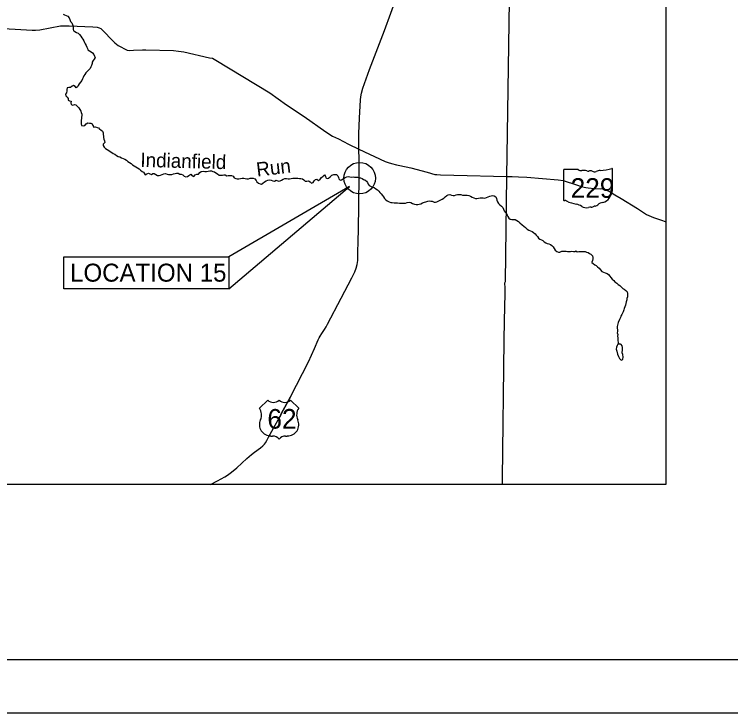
# Model space of a CAD drawing. Extents: x -12.1 to 34, y 0 to 22.
# Drawn here: x 4.28 to 11.05, y 0 to 6.6 of the extents above; entities that cross this region are included whole.
import ezdxf

# ---------------------------------------------------------------- set-up
doc = ezdxf.new("R2010")
doc.units = 0
for name, color, linetype in [('BR_P_Gen_Text', 7, 'Continuous'), ('Default', 7, 'Continuous'), ('GM_X_County_Road', 7, 'Continuous'), ('GM_X_Minor_Lake', 7, 'Continuous'), ('GM_X_Minor_River', 7, 'Continuous'), ('GM_X_Minor_River_Text', 7, 'Continuous'), ('GM_X_State_Route', 7, 'Continuous'), ('GM_X_State_Shield', 7, 'Continuous'), ('GM_X_Township', 7, 'Continuous'), ('GM_X_US_Route', 7, 'Continuous'), ('GM_X_US_Shield', 7, 'Continuous'), ('SH_Border', 7, 'Continuous'), ('SH_Cut_Line', 7, 'Continuous'), ('SH_Text', 7, 'Continuous')]:
    doc.layers.add(name, color=color, linetype=linetype)

msp = doc.modelspace()

# ---------------------------------------------------------------- linework, layer by layer
at = {"layer": 'BR_P_Gen_Text'}
for points in [[(6.3039, 4.3094), (6.3039, 4.0092), (7.4481, 4.9757)], [(4.7437, 4.3094), (6.3039, 4.3094), (6.3039, 4.0092), (4.7437, 4.0092)]]:
    msp.add_lwpolyline(points, close=True, dxfattribs=at)
at = {"layer": 'Default'}
msp.add_circle((7.5423, 5.0544), 0.149, dxfattribs=at)
at = {"layer": 'GM_X_County_Road'}
msp.add_lwpolyline([(6.8881, 2.9878), (6.8011, 2.8263), (6.791, 2.8012)], dxfattribs=at)
at = {"layer": 'GM_X_Minor_Lake'}
for points in [[(9.9847, 3.4834), (9.9767, 3.4716), (9.9714, 3.4577), (9.9688, 3.438), (9.9736, 3.4171), (9.9822, 3.3899), (9.9897, 3.3669), (9.9998, 3.3499), (10.0116, 3.3365), (10.0206, 3.3344), (10.0302, 3.3435), (10.0334, 3.3611), (10.0307, 3.3857), (10.0264, 3.4028), (10.028, 3.4305), (10.029, 3.4546), (10.0242, 3.469), (10.0167, 3.4808), (10.0103, 3.4861), (10.0039, 3.4855)], [(10.0039, 3.4855), (9.9847, 3.4834)]]:
    msp.add_lwpolyline(points, dxfattribs=at)
at = {"layer": 'GM_X_Minor_River'}
for points in [[(4.7387, 6.6063), (4.752, 6.5999), (4.7675, 6.5919), (4.784, 6.585), (4.7968, 6.5711), (4.8022, 6.5556), (4.8086, 6.5364), (4.8193, 6.522), (4.8279, 6.5071), (4.8327, 6.491), (4.8327, 6.4761), (4.8322, 6.4627), (4.8365, 6.4489), (4.8498, 6.4409), (4.8663, 6.4323), (4.8802, 6.4254), (4.8941, 6.4137), (4.9048, 6.3971), (4.916, 6.3822), (4.9235, 6.3688), (4.9342, 6.3528), (4.9406, 6.3378), (4.9481, 6.324), (4.9572, 6.3085), (4.9636, 6.2946), (4.9679, 6.2813), (4.9716, 6.2679), (4.9871, 6.2588), (5.0031, 6.2498), (5.0175, 6.2396), (5.0287, 6.2242), (5.0357, 6.2081), (5.0399, 6.1942), (5.032, 6.1793), (5.0219, 6.1659), (5.0139, 6.152), (5.0123, 6.1376), (5.0054, 6.121), (4.9996, 6.1071), (4.9937, 6.0927), (4.982, 6.0794), (4.9687, 6.0655), (4.9538, 6.051), (4.9432, 6.0345), (4.9341, 6.0211), (4.9278, 6.0061), (4.923, 5.9928), (4.9166, 5.9783), (4.9033, 5.9623), (4.8905, 5.9463), (4.882, 5.9308), (4.8757, 5.9174), (4.8618, 5.9094), (4.8538, 5.9227), (4.8378, 5.9318), (4.8234, 5.9249), (4.8069, 5.9115), (4.792, 5.9104), (4.7765, 5.9077), (4.7739, 5.8933), (4.7744, 5.8789), (4.7707, 5.8628), (4.7596, 5.8489), (4.7639, 5.8329), (4.7777, 5.8217), (4.7847, 5.8073), (4.7852, 5.7913), (4.8002, 5.787), (4.814, 5.7822), (4.8109, 5.7657)], [(4.8109, 5.7657), (4.8152, 5.7518), (4.8301, 5.7459), (4.8461, 5.7502), (4.8599, 5.7481), (4.8722, 5.7347), (4.8872, 5.7198), (4.8978, 5.7043), (4.9059, 5.6883), (4.9102, 5.6744), (4.9139, 5.66), (4.9139, 5.6461), (4.9129, 5.6322), (4.9113, 5.6178), (4.9097, 5.6039), (4.9076, 5.5836), (4.9077, 5.5671), (4.913, 5.5537), (4.9274, 5.5484), (4.9423, 5.5527), (4.9562, 5.5676), (4.9711, 5.5773), (4.9865, 5.5757), (4.9999, 5.5735), (5.0132, 5.5688), (5.0207, 5.5517), (5.0303, 5.5383), (5.0452, 5.5389), (5.0602, 5.533), (5.0745, 5.5309), (5.0815, 5.517), (5.0959, 5.5111), (5.1103, 5.4983), (5.1173, 5.4823), (5.1173, 5.4684), (5.1216, 5.4529), (5.12, 5.4385), (5.1243, 5.4236), (5.1312, 5.4075), (5.1313, 5.3915), (5.1158, 5.376), (5.1158, 5.3621), (5.1265, 5.3482), (5.1404, 5.3344), (5.1564, 5.3242), (5.1703, 5.3157), (5.1842, 5.3077), (5.1991, 5.2976), (5.2124, 5.289), (5.2268, 5.2805), (5.2434, 5.2698), (5.2594, 5.2597), (5.2743, 5.2549), (5.2914, 5.2474), (5.3074, 5.241), (5.3218, 5.2352), (5.3378, 5.224), (5.3511, 5.2133), (5.3656, 5.2032), (5.381, 5.1925), (5.396, 5.1813), (5.4109, 5.1712), (5.4258, 5.1632), (5.4419, 5.1525), (5.4573, 5.1429), (5.4707, 5.1306), (5.4851, 5.1189), (5.4995, 5.1114), (5.5155, 5.0847), (5.531, 5.0943), (5.5453, 5.1008), (5.5587, 5.0944), (5.5731, 5.0885), (5.5869, 5.0997), (5.6002, 5.0992), (5.6136, 5.0896), (5.6301, 5.08), (5.6456, 5.0784), (5.6594, 5.0832), (5.6738, 5.0891), (5.6893, 5.0961), (5.7069, 5.0977), (5.7213, 5.0929), (5.7362, 5.0881), (5.7511, 5.0886), (5.7666, 5.0897), (5.782, 5.0945), (5.7964, 5.0999), (5.8097, 5.1015), (5.8262, 5.1005), (5.8412, 5.0909), (5.855, 5.0919), (5.8694, 5.0866), (5.8839, 5.0727), (5.8993, 5.0679), (5.9142, 5.0695), (5.9286, 5.0808), (5.9451, 5.0931), (5.9601, 5.076), (5.975, 5.0717), (5.9872, 5.0867)], [(5.9872, 5.0867), (6.0032, 5.0937), (6.0171, 5.0931), (6.0314, 5.107), (6.0453, 5.1183), (6.0618, 5.1215), (6.0773, 5.1178), (6.0933, 5.1178), (6.1108, 5.1221), (6.1247, 5.1237), (6.1407, 5.1226), (6.1556, 5.1183), (6.169, 5.1157), (6.1834, 5.1061), (6.1994, 5.0943), (6.2148, 5.0831), (6.2287, 5.0816), (6.2442, 5.0832), (6.258, 5.0858), (6.2719, 5.0848), (6.2852, 5.0763), (6.3001, 5.0784), (6.3172, 5.0811), (6.3305, 5.0806), (6.3449, 5.072), (6.3551, 5.0581), (6.3705, 5.0507), (6.3849, 5.0486), (6.4009, 5.0486), (6.4169, 5.0502), (6.4318, 5.0539), (6.4462, 5.0539), (6.4612, 5.0513), (6.4755, 5.0486), (6.4926, 5.0497), (6.5065, 5.0545), (6.523, 5.0545), (6.5363, 5.054), (6.5507, 5.0476), (6.5635, 5.0321), (6.5715, 5.0183), (6.5865, 5.0071), (6.6003, 5.0007), (6.6137, 4.9991), (6.6275, 5.0076), (6.6435, 5.0183), (6.6573, 5.0295), (6.6739, 5.0349), (6.6888, 5.0376), (6.7048, 5.036), (6.7213, 5.028), (6.7373, 5.0264), (6.7517, 5.0355), (6.7757, 5.0275), (6.7901, 5.0291), (6.8039, 5.0371), (6.8188, 5.0457), (6.8364, 5.0521), (6.8513, 5.0511), (6.8663, 5.0495), (6.8796, 5.0484), (6.8961, 5.0506), (6.911, 5.0543), (6.9254, 5.0549), (6.943, 5.0549), (6.9579, 5.0538), (6.9723, 5.0522), (6.9856, 5.0506), (7.0027, 5.048), (7.0161, 5.0384), (7.0278, 5.025), (7.0433, 5.0256), (7.0598, 5.0288), (7.0747, 5.0197), (7.0881, 5.008), (7.1019, 5.0133), (7.1136, 5.0278), (7.1248, 5.0411), (7.1392, 5.046), (7.1541, 5.0331), (7.168, 5.0438), (7.1813, 5.0604), (7.1962, 5.0732), (7.2105, 5.085), (7.2191, 5.0711), (7.2212, 5.0567), (7.2356, 5.0514), (7.249, 5.0551), (7.2628, 5.0685), (7.2798, 5.0824), (7.2969, 5.0877), (7.3102, 5.0883), (7.3241, 5.0888), (7.3353, 5.0755), (7.3422, 5.0611), (7.3449, 5.0477), (7.3572, 5.0344), (7.371, 5.0376), (7.387, 5.0494), (7.4051, 5.0595), (7.4216, 5.0675)], [(7.4216, 5.0675), (7.4355, 5.0702), (7.4494, 5.0686), (7.4659, 5.0649), (7.4797, 5.0676), (7.4941, 5.0649), (7.508, 5.065), (7.5219, 5.0639), (7.5368, 5.0591), (7.5512, 5.057), (7.5651, 5.05), (7.5784, 5.0431), (7.5928, 5.0378), (7.6083, 5.0276), (7.6173, 5.0127), (7.6232, 4.9993), (7.6312, 4.9849), (7.6499, 4.9743), (7.6654, 4.9684), (7.6787, 4.9647), (7.6963, 4.9551), (7.7102, 4.9449), (7.723, 4.9316), (7.7348, 4.9183), (7.747, 4.9049), (7.7582, 4.8905), (7.7684, 4.8772), (7.7775, 4.8622), (7.7898, 4.8489), (7.8042, 4.8398), (7.8202, 4.8313), (7.8372, 4.8254), (7.8516, 4.8259), (7.8687, 4.8222), (7.8847, 4.8222), (7.9001, 4.8206), (7.9199, 4.8191), (7.9359, 4.818), (7.9513, 4.8175), (7.9769, 4.8191), (7.9934, 4.825), (8.0099, 4.8272), (8.0254, 4.8245), (8.0435, 4.8149), (8.0617, 4.8085), (8.0755, 4.8064), (8.0915, 4.8069), (8.1054, 4.808), (8.1219, 4.8128), (8.1379, 4.8198), (8.1549, 4.8262), (8.1682, 4.83), (8.1864, 4.8369), (8.2007, 4.8396), (8.2157, 4.838), (8.2295, 4.8364), (8.2461, 4.8274), (8.2599, 4.8274), (8.2738, 4.8306), (8.2903, 4.8386), (8.3041, 4.8461), (8.3228, 4.8552), (8.3382, 4.8664), (8.3521, 4.8777), (8.367, 4.8894), (8.3808, 4.8964), (8.3952, 4.8991), (8.4107, 4.8927), (8.4261, 4.8895), (8.44, 4.8906), (8.4549, 4.8959), (8.4688, 4.9002), (8.4837, 4.9007), (8.5008, 4.8986), (8.5141, 4.8949), (8.529, 4.8922), (8.5455, 4.8933), (8.5589, 4.8949), (8.5759, 4.8912), (8.5903, 4.8843), (8.6079, 4.8752), (8.6218, 4.8677), (8.6383, 4.8608), (8.6517, 4.8608), (8.6676, 4.8646), (8.6815, 4.8694), (8.6948, 4.8699), (8.7098, 4.8678), (8.7263, 4.8662), (8.7593, 4.878), (8.7732, 4.885), (8.7865, 4.8877), (8.8003, 4.8909), (8.8147, 4.8882), (8.8291, 4.877), (8.8361, 4.861), (8.8398, 4.845), (8.8468, 4.8295), (8.8564, 4.8161), (8.8676, 4.8028), (8.8826, 4.7884)], [(8.8826, 4.7884), (8.8981, 4.7761), (8.9023, 4.7628), (8.9088, 4.7468), (8.9189, 4.7334), (8.9317, 4.719), (8.9387, 4.7051), (8.9451, 4.6912), (8.9531, 4.6768), (8.967, 4.6678), (8.9803, 4.6635), (8.9968, 4.6624), (9.0139, 4.6625), (9.0304, 4.655), (9.0454, 4.6449), (9.0587, 4.6336), (9.0801, 4.6139), (9.0955, 4.6011), (9.1121, 4.5867), (9.127, 4.5728), (9.1409, 4.5643), (9.1569, 4.5579), (9.1724, 4.5515), (9.1868, 4.5414), (9.2028, 4.5291), (9.2124, 4.5157), (9.2236, 4.5019), (9.2338, 4.488), (9.2476, 4.4768), (9.261, 4.4715), (9.2743, 4.464), (9.2887, 4.4538), (9.3026, 4.4426), (9.317, 4.4373), (9.3319, 4.4347), (9.3463, 4.4272), (9.3602, 4.4171), (9.3741, 4.4042), (9.3821, 4.3888), (9.3928, 4.3738), (9.4061, 4.361), (9.4221, 4.3546), (9.4365, 4.3552), (9.453, 4.3648), (9.4664, 4.3653), (9.4802, 4.3632), (9.4946, 4.3632), (9.5079, 4.3606), (9.5223, 4.3595), (9.5357, 4.3622), (9.5506, 4.3627), (9.566, 4.3622), (9.5799, 4.3622), (9.5868, 4.3689)], [(9.5868, 4.3689), (9.6007, 4.3574), (9.6156, 4.3612), (9.6311, 4.3607), (9.6449, 4.3623), (9.6593, 4.3607), (9.6737, 4.3596), (9.6876, 4.3554), (9.7025, 4.3506), (9.7164, 4.3431), (9.7297, 4.3351), (9.7431, 4.3207), (9.7479, 4.3052), (9.7463, 4.2903), (9.7431, 4.2759), (9.7378, 4.2609), (9.737, 4.2584)], [(9.737, 4.2584), (9.7512, 4.2481), (9.7656, 4.2347), (9.7789, 4.2289), (9.7928, 4.2166), (9.8067, 4.2049), (9.8195, 4.1883), (9.8323, 4.1728), (9.8483, 4.1664), (9.8638, 4.1601), (9.8819, 4.1515), (9.8958, 4.1425), (9.9086, 4.1286), (9.9182, 4.1147), (9.93, 4.0992), (9.9449, 4.088), (9.9556, 4.0747), (9.9732, 4.0608), (9.9871, 4.0501), (10.0015, 4.0395), (10.0175, 4.0234), (10.0319, 4.0106), (10.0452, 4.0058), (10.0596, 3.993), (10.0709, 3.9786), (10.0752, 3.9637), (10.0768, 3.9466), (10.0741, 3.9316), (10.0699, 3.9172), (10.0683, 3.9028), (10.0641, 3.8841), (10.0598, 3.8691), (10.0567, 3.8542), (10.0513, 3.8392), (10.045, 3.8232), (10.0407, 3.8082), (10.0344, 3.7916), (10.0285, 3.7783), (10.0216, 3.7639), (10.0136, 3.7489), (10.0078, 3.7355), (10.0004, 3.719), (9.9876, 3.6901), (9.9796, 3.6655), (9.9791, 3.6516), (9.9792, 3.6351), (9.9813, 3.6207), (9.9803, 3.6052), (9.9782, 3.5908), (9.983, 3.5758), (9.9819, 3.5614), (9.9836, 3.5438), (9.9846, 3.5267), (9.9879, 3.4935), (9.9928, 3.4843)]]:
    msp.add_lwpolyline(points, dxfattribs=at)
at = {"layer": 'GM_X_State_Route'}
for points in [[(4.0631, 6.4753), (4.4465, 6.4537), (4.4768, 6.4538), (4.5184, 6.4576), (4.7139, 6.494), (4.7437, 6.4963), (4.7949, 6.4953), (5.0204, 6.4842), (5.0609, 6.4828), (5.0791, 6.4759), (5.094, 6.4684), (5.2272, 6.3347), (5.2593, 6.3097), (5.3436, 6.2661), (5.3628, 6.2619), (5.4033, 6.2641), (5.4875, 6.2681), (5.5025, 6.2682), (5.5201, 6.2677), (5.7829, 6.261), (5.8282, 6.2552), (5.881, 6.2479), (6.1237, 6.1935), (6.1498, 6.1883), (6.1813, 6.1718), (6.6928, 5.8601), (6.8516, 5.7467), (7.0172, 5.6375), (7.2241, 5.4912), (7.287, 5.4526), (7.3413, 5.4251), (7.4385, 5.3758), (7.5333, 5.3273)], [(7.5333, 5.3273), (7.7854, 5.2127), (7.8129, 5.2018), (7.8435, 5.1919), (7.8898, 5.182), (7.922, 5.1737), (8.025, 5.151), (8.1802, 5.1109), (8.2544, 5.0906), (8.2739, 5.0883), (8.3074, 5.0866), (8.434, 5.0831), (8.9338, 5.0696), (8.9842, 5.0687)], [(8.9842, 5.0687), (9.0457, 5.067), (9.1239, 5.064), (9.419, 5.0399), (9.4658, 5.0319), (9.5928, 4.9905), (9.6388, 4.9755), (9.6808, 4.9652), (9.7041, 4.9624), (9.7649, 4.9574), (9.8228, 4.9533), (9.8292, 4.9574), (9.8553, 4.9462), (9.874, 4.9407), (9.8911, 4.9336), (9.9113, 4.9243), (9.9559, 4.8984), (10.0145, 4.8636), (10.169, 4.7676), (10.2557, 4.7121), (10.3226, 4.6836), (10.4062, 4.6536), (10.4394, 4.642)]]:
    msp.add_lwpolyline(points, dxfattribs=at)
at = {"layer": 'GM_X_State_Shield'}
for p, q in [((9.4699, 5.1303), (9.4699, 4.8489)), ((9.6102, 5.1351), (9.4744, 5.1351)), ((9.9333, 4.9949), (9.9333, 5.1421)), ((9.9333, 4.9949), (9.9333, 4.9949))]:
    msp.add_line(p, q, dxfattribs=at)
for centre, major_axis, start_param, end_param in [((9.4752, 5.1309), (0.00537, 0), 1.712693, 3.28349), ((9.6425, 5.1678), (0.0521, 0), 4.042523, 4.731795), ((9.6598, 4.9771), (0.187, 0), 1.404758, 1.657858), ((9.7022, 5.1323), (0.015, 0), 3.836095, 5.185415), ((9.7243, 5.0998), (0.0312, 0), 0.950623, 2.079405), ((9.7646, 5.1444), (0.0376, 0), 4.081561, 5.145723), ((9.8309, 5.0492), (0.0989, 0), 1.699011, 2.107814), ((9.7682, 5.5188), (0.4915, 0), 4.814394, 5.042369), ((9.9282, 5.1427), (0.00516, 0), 6.141152, 7.989035), ((9.9518, 4.9333), (0.0349, 0), 2.387724, 3.262537), ((9.9322, 4.9841), (0.00798, 0), 1.883978, 3.671073), ((9.8814, 4.9655), (0.0479, 0), 5.934695, 6.695948), ((9.9278, 4.9943), (0.00552, 0), 5.05454, 6.418171), ((9.7958, 4.9145), (0.1229, 0), 5.101752, 6.440018), ((9.4752, 4.8482), (0.00542, 0), 3.00124, 4.508301), ((9.476, 4.877), (0.0413, 0), 4.665946, 4.897461), ((9.4845, 4.8326), (0.0149, 0), 0.519207, 1.627899), ((9.6727, 5.0855), (0.3549, 0), 4.195997, 4.488961), ((9.8476, 4.7698), (0.0673, 0), 1.647645, 2.488434), ((9.5669, 4.7224), (0.1111, 0), 0.823519, 1.323587), ((9.687, 4.8312), (0.0705, 0), 4.026481, 4.996735), ((9.7277, 4.7339), (0.0579, 0), 1.495662, 1.94098), ((9.7329, 4.8101), (0.0375, 0), 4.691044, 5.507374), ((9.7668, 4.7829), (0.0106, 0), 1.147584, 2.315152), ((9.7623, 4.8216), (0.0397, 0), 4.937069, 5.64225)]:
    msp.add_ellipse(centre, major_axis=major_axis, ratio=0.8, start_param=start_param, end_param=end_param, dxfattribs=at)
at = {"layer": 'GM_X_Township'}
msp.add_lwpolyline([(8.8923, 2.1565), (8.8936, 2.2148), (8.9101, 3.5189), (8.913, 3.7042), (8.9183, 3.9633), (8.9176, 4.0271), (8.9142, 4.0522), (8.9156, 4.0653), (8.9204, 4.0765), (8.9335, 5.0704), (8.9403, 5.4765), (8.991, 8.8216), (9.0041, 9.1707)], dxfattribs=at)
at = {"layer": 'GM_X_US_Route'}
for points in [[(7.5333, 5.3273), (7.5348, 5.4775), (7.5416, 5.6216), (7.5502, 5.7937), (7.5534, 5.8223), (7.5595, 5.8578), (7.5734, 5.9053), (7.6363, 6.0808), (7.6986, 6.2452), (7.7785, 6.4524), (7.9568, 6.9465)], [(6.8881, 2.9878), (7.0602, 3.3162), (7.1163, 3.4446), (7.1496, 3.5263), (7.1592, 3.5455), (7.1684, 3.5615), (7.1838, 3.5849), (7.2098, 3.6238), (7.2258, 3.6485), (7.2397, 3.6741), (7.3677, 3.9199), (7.4695, 4.1133), (7.4849, 4.1423), (7.4978, 4.1703), (7.5105, 4.2037), (7.5188, 4.2388), (7.524, 4.2761), (7.5262, 4.3391), (7.5299, 4.4708), (7.5314, 4.5577), (7.5389, 5.0679), (7.5385, 5.1475), (7.5367, 5.2314), (7.5333, 5.3273)], [(6.791, 2.8012), (6.8011, 2.8263), (6.8881, 2.9878)], [(6.1313, 2.1565), (6.1996, 2.1927), (6.2675, 2.2309), (6.2937, 2.246), (6.3184, 2.2633), (6.3477, 2.2855), (6.3819, 2.3167), (6.4772, 2.4043), (6.519, 2.4419), (6.5488, 2.4641), (6.6055, 2.5039), (6.6271, 2.5221), (6.6425, 2.5384), (6.6527, 2.5532), (6.6644, 2.5724), (6.6805, 2.6042), (6.7421, 2.7192), (6.771, 2.7702), (6.791, 2.8012)]]:
    msp.add_lwpolyline(points, dxfattribs=at)
at = {"layer": 'GM_X_US_Shield'}
for p, q in [((6.6728, 2.9562), (6.5955, 2.879)), ((6.9663, 2.879), (6.8891, 2.9562)), ((6.7037, 2.6163), (6.7191, 2.6163)), ((6.8427, 2.6163), (6.8582, 2.6163))]:
    msp.add_line(p, q, dxfattribs=at)
for centre, radius, start, end in [((6.7269, 3.0114), 0.0772, 225.573, 314.427), ((6.835, 3.0114), 0.0772, 225.573, 314.427), ((6.5069, 2.817), 0.1081, 334.54712, 35.00093), ((7.0549, 2.817), 0.1081, 144.99907, 205.45288), ((6.7025, 2.7245), 0.1081, 154.83192, 270.63826), ((6.8594, 2.7245), 0.1081, 269.36174, 25.16808), ((6.7191, 2.5391), 0.0772, 36.8699, 90), ((6.8427, 2.5391), 0.0772, 90, 143.1301)]:
    msp.add_arc(centre, radius, start, end, dxfattribs=at)
at = {"layer": 'SH_Border'}
msp.add_lwpolyline([(1.5, 21.5), (33.5, 21.5), (33.5, 0.5), (1.5, 0.5)], close=True, dxfattribs=at)
at = {"layer": 'SH_Cut_Line'}
msp.add_lwpolyline([(0, 0), (34, 0), (34, 22), (0, 22)], close=True, dxfattribs=at)
at = {"layer": 'SH_Text'}
msp.add_lwpolyline([(3.2217, 9.5741), (10.4394, 9.5741), (10.4394, 2.1565), (3.2217, 2.1565)], close=True, dxfattribs=at)

# ---------------------------------------------------------------- texts
at = {"layer": 'BR_P_Gen_Text'}
msp.add_text('LOCATION 15', height=0.17, dxfattribs=at).set_placement((4.8045, 4.076))
at = {"layer": 'GM_X_Minor_River_Text'}
for s, height, rotation, p in [('Indianfield', 0.133176, 358.42331, (5.4678, 5.1619)), ('Run', 0.13317, 6.81938, (6.5733, 5.069))]:
    msp.add_text(s, height=height, rotation=rotation, dxfattribs=at).set_placement(p)
at = {"layer": 'GM_X_State_Shield'}
msp.add_text('229', height=0.18539, dxfattribs=at).set_placement((9.538, 4.8687))
at = {"layer": 'GM_X_US_Shield'}
msp.add_text('62', height=0.18539, dxfattribs=at).set_placement((6.6702, 2.6859))

doc.saveas('drawing.dxf')
